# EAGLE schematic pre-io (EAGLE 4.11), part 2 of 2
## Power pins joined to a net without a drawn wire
-15V: A05.B2(-15V) A06.B2(-15V) A07.B2(-15V) A08.B2(-15V) A09.B2(-15V) A10.B2(-15V) A12.B2(-15V) A13.B2(-15V) A14.B2(-15V) A15.B2(-15V) A16.B2(-15V) A17.B2(-15V) A18.B2(-15V) A20.B2(-15V) A21.B2(-15V) A22.B2(-15V) A23.B2(-15V) A24.B2(-15V) A25.B2(-15V) A26.B2(-15V) A27.B2(-15V) A28.B2(-15V) A29.B2(-15V) A30.B2(-15V) A31.B2(-15V) A32.B2(-15V) A33.B2(-15V) A34.B2(-15V) A35.B2(-15V) A36.B2(-15V) A38.B2(-15V) A39.B2(-15V) A40.B2(-15V) B03.B2(-15V) B05.B2(-15V) B06.B2(-15V) B07.B2(-15V) B08.B2(-15V) B09.B2(-15V) B10.B2(-15V) B11.B2(-15V) B12.B2(-15V) B13.B2(-15V) B14.B2(-15V) B15.B2(-15V) B16.B2(-15V) B17.B2(-15V) B18.B2(-15V) B19.B2(-15V) B20.B2(-15V) B21.B2(-15V) B22.B2(-15V) B23.B2(-15V) B24.B2(-15V) B25.B2(-15V) B26.B2(-15V) B27.B2(-15V) B28.B2(-15V) B29.B2(-15V) B30.B2(-15V) B31.B2(-15V) B32.B2(-15V) B33.B2(-15V) B34.B2(-15V) B35.B2(-15V) B36.B2(-15V) B37.B2(-15V) B40.B2(-15V) C03.B2(-15V) C04.B2(-15V) C05.B2(-15V) C06.B2(-15V) C07.B2(-15V) C08.B2(-15V) C09.B2(-15V) C10.B2(-15V) C11.B2(-15V) C12.B2(-15V) C13.B2(-15V) C14.B2(-15V) C21.B2(-15V) C22.B2(B:-15V) C23.B2(-15V) C24.B2(-15V) C25.B2(B:-15V) C26.B2(-15V) C27.B2(B:-15V) C30.B2(-15V) C33.B2 C34.B2 C35.B2 C36.B2(-15V) C37.B2(-15V) C38.B2(-15V) C39.B2(-15V) D06.B2(-15V) D06A.B2(-15V) D07.B2(-15V) D08.B2(-15V) D09.B2(-15V) D10.B2(-15V) D11.B2(-15V) D12.B2(-15V) D13.B2(-15V) D14.B2(-15V) D15.B2(-15V) D16.B2(-15V) D17.B2(-15V) D18.B2(-15V) D19.B2(-15V) D20.B2(-15V) D21.B2(-15V) D22.B2(-15V) D23.B2 D24.B2 D25.B2 D26.B2 D27.B2(-15V) D33.B2 D34.B2 D35.B2 E03.B2(-15V) E05.B2(-15V) E06.B2(-15V) E07.B2(-15V) E09.B2(-15V) E10.B2(-15V) E11.B2(-15V) E12.B2(-15V) E13.B2(-15V) E14.B2(-15V) E15.B2(-15V) E16.B2(-15V) E17.B2(-15V) E18.B2(-15V) E19.B2(-15V) E20.B2(-15V) E21.B2 E22.B2 E23.B2 E24.B2 E25.B2 E26.B2 E27.B2 E28.B2 E33.B2 E34.B2 E35.B2 F03.B2(-15V) F05.B2(-15V) F06.B2(-15V) F07.B2(-15V) F08.B2(-15V) F09.B2(-15V) F10.B2(-15V) F11.B2(-15V) F12.B2(-15V) F13.B2(-15V) F14.B2(-15V) F15.B2(-15V) F16.B2(-15V) F17.B2(-15V) F18.B2(-15V) F19.B2(-15V) F20.B2(-15V) F21.B2 F22.B2 F22A.B2(-15V) F23.B2 F24.B2 F25.B2 F26.B2 F27.B2 F28.B2 F33.B2 F34.B2 F35.B2 F36.B2(-15V) F37.B2(-15V) F38.B2(-15V) F39.B2(-15V)
GND: A05.C2(GND) A06.C2(GND) A07.C2(GND) A08.C2(GND) A09.C2(GND) A10.C2(GND) A12.C2(GND) A13.C2(GND) A14.C2(GND) A15.C2(GND) A16.C2(K:GND) A17.C2(GND) A18.C2(GND) A20.C2(GND) A21.C2(GND) A22.C2(GND) A23.C2(GND) A24.C2(GND) A25.C2(GND) A26.C2(GND) A27.C2(GND) A29.C2(GND) A30.C2(GND) A31.C2(GND) A32.C2(GND) A33.C2(GND) A34.C2(GND) A35.C2(GND) A36.C2(GND) A38.C2(GND) A39.C2(GND) A40.C2(GND) B03.C2(GND) B05.C2(GND) B06.C2(GND) B07.C2(GND) B08.C2(GND) B09.C2(GND) B10.C2(GND) B11.C2(GND) B12.C2(GND) B13.C2(GND) B14.C2(GND) B15.C2(GND) B16.C2(GND) B17.C2(GND) B18.C2(GND) B19.C2(GND) B20.C2(GND) B21.C2(GND) B22.C2(GND) B23.C2(GND) B24.C2(GND) B25.C2(GND) B26.C2(GND) B28.C2(GND) B29.C2(GND) B30.C2(GND) B31.C2(GND) B32.C2(GND) B33.C2(GND) B34.C2(GND) B35.C2(GND) B36.C2(GND) B37.C2(GND) B40.C2(GND) C03.C2(GND) C05.C2(GND) C06.C2(GND) C07.C2(GND) C08.C2(GND) C09.C2(GND) C10.C2(GND) C11.C2(GND) C12.C2(GND) C13.C2(GND) C14.C2(GND) C21.C2(GND) C22.C2(C2:GND) C22.T2(T:GND) C22.U2(U:GND) C23.C2(GND) C24.C2(GND) C25.C2(C2:GND) C25.T2(T:GND) C25.U2(U:GND) C26.C2(GND) C27.C2(C2:GND) C27.T2(T:GND) C27.U2(U:GND) C30.C2(GND) C33.C2 C34.C2 C35.C2 C36.C2(GND) C37.C2(GND) C38.C2(K:GND) C39.C2(GND) C39.V2(V:GND) D06.C2(GND) D06A.C2(GND) D07.C2(GND) D08.C2(GND) D09.C2(GND) D10.C2(GND) D11.C2(GND) D12.C2(GND) D13.C2(GND) D14.C2(GND) D15.C2(GND) D16.C2(GND) D17.C2(GND) D18.C2(GND) D19.C2(GND) D20.C2(GND) D21.C2(GND) D22.C2(GND) D23.C2 D24.C2 D25.C2 D26.C2 D27.C2(GND) D33.C2 D34.C2 D35.C2 E03.C2(GND) E05.C2(GND) E05.V2(V:GND) E06.C2(GND) E07.C2(GND) E09.C2(GND) E10.C2(GND) E11.C2(GND) E12.C2(GND) E13.C2(GND) E14.C2(GND) E15.C2(GND) E16.C2(GND) E17.C2(GND) E18.C2(GND) E19.C2(GND) E20.C2(GND) E21.C2 E22.C2 E23.C2 E24.C2 E25.C2 E26.C2 E27.C2 E28.C2 E33.C2 E34.C2 E35.C2 F03.C2(GND) F05.C2(GND) F06.C2(GND) F07.C2(GND) F08.C2(GND) F09.C2(GND) F10.C2(GND) F11.C2(GND) F12.C2(GND) F13.C2(GND) F14.C2(GND) F15.C2(GND) F16.C2(GND) F17.C2(GND) F18.C2(GND) F19.C2(GND) F20.C2(GND) F21.C2 F22.C2 F22A.C2(GND) F23.C2 F24.C2 F25.C2 F26.C2 F27.C2 F28.C2 F33.C2 F34.C2 F35.C2 F36.C2(GND) F37.C2(K:GND) F38.C2(K:GND) F39.C2(K:GND)
VCC: A05.A2(VCC) A06.A2(VCC) A07.A2(VCC) A08.A2(VCC) A09.A2(VCC) A10.A2(VCC) A12.A2(VCC) A13.A2(VCC) A14.A2(VCC) A15.A2(VCC) A16.A2(VCC) A17.A2(VCC) A18.A2(VCC) A20.A2(VCC) A21.A2(VCC) A22.A2(VCC) A23.A2(VCC) A24.A2(VCC) A25.A2(VCC) A26.A2(VCC) A27.A2(VCC) A28.A2(VCC) A29.A2(VCC) A30.A2(VCC) A31.A2(VCC) A32.A2(VCC) A33.A2(VCC) A34.A2(VCC) A35.A2(VCC) A36.A2(VCC) A38.A2(VCC) A39.A2(VCC) A40.A2(VCC) B03.A2(VCC) B05.A2(VCC) B06.A2(VCC) B07.A2(VCC) B08.A2(VCC) B09.A2(VCC) B10.A2(VCC) B11.A2(VCC) B12.A2(VCC) B13.A2(VCC) B14.A2(VCC) B15.A2(VCC) B16.A2(VCC) B17.A2(VCC) B18.A2(VCC) B19.A2(VCC) B20.A2(VCC) B21.A2(VCC) B22.A2(VCC) B23.A2(VCC) B24.A2(VCC) B25.A2(VCC) B26.A2(VCC) B27.A2(VCC) B28.A2(VCC) B29.A2(VCC) B30.A2(VCC) B31.A2(VCC) B32.A2(VCC) B33.A2(VCC) B34.A2(VCC) B35.A2(VCC) B36.A2(VCC) B37.A2(VCC) B40.A2(VCC) C03.A2(VCC) C04.A2(VCC) C05.A2(VCC) C06.A2(VCC) C07.A2(VCC) C08.A2(VCC) C09.A2(VCC) C10.A2(VCC) C11.A2(VCC) C12.A2(VCC) C13.A2(VCC) C14.A2(VCC) C21.A2(VCC) C22.A2(C2:VCC) C23.A2(VCC) C24.A2(VCC) C25.A2(C2:VCC) C26.A2(VCC) C27.A2(C2:VCC) C30.A2(VCC) C33.A2 C34.A2 C35.A2 C36.A2(VCC) C37.A2(VCC) C38.A2(VCC) C39.A2(VCC) D06.A2(VCC) D06A.A2(VCC) D07.A2(VCC) D08.A2(VCC) D09.A2(VCC) D10.A2(VCC) D11.A2(VCC) D12.A2(VCC) D13.A2(VCC) D14.A2(VCC) D15.A2(VCC) D16.A2(VCC) D17.A2(VCC) D18.A2(VCC) D19.A2(VCC) D20.A2(VCC) D21.A2(VCC) D22.A2(VCC) D23.A2 D24.A2 D25.A2 D26.A2 D27.A2(VCC) D33.A2 D34.A2 D35.A2 E03.A2(VCC) E05.A2(VCC) E06.A2(VCC) E07.A2(VCC) E09.A2(VCC) E10.A2(VCC) E11.A2(VCC) E12.A2(VCC) E13.A2(VCC) E14.A2(VCC) E15.A2(VCC) E16.A2(VCC) E17.A2(VCC) E18.A2(VCC) E19.A2(VCC) E20.A2(VCC) E21.A2 E22.A2 E23.A2 E24.A2 E25.A2 E26.A2 E27.A2 E28.A2 E33.A2 E34.A2 E35.A2 F03.A2(VCC) F05.A2(VCC) F06.A2(VCC) F07.A2(VCC) F08.A2(VCC) F09.A2(VCC) F10.A2(VCC) F11.A2(VCC) F12.A2(VCC) F13.A2(VCC) F14.A2(VCC) F15.A2(VCC) F16.A2(VCC) F17.A2(VCC) F18.A2(VCC) F19.A2(VCC) F20.A2(VCC) F21.A2 F22.A2 F22A.A2(VCC) F23.A2 F24.A2 F25.A2 F26.A2 F27.A2 F28.A2 F33.A2 F34.A2 F35.A2 F36.A2(VCC) F37.A2(VCC) F38.A2(VCC) F39.A2(VCC)

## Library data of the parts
A01 A02 B01 B02 C01 C02 C28 D01 D02 D28 E01 E02 F01 F02 = dec-r:W023: One-sided 18 pin connector/cable.
A05-A07 B06 B07 C03 C06 E07 = dec-r:W050: Indicator Driver
A08 A10 A15 A26 A27 B15 B17 B24 B25 B36 C14 D06 D06A D07 D08 E09 E10 E11 E13 E14 F14 F36 = dec-r:R113: Diode Gate
A09 A17 A18 A24 A40 B08 B16 B33 B37 C05 C09 C13 C21 C24 C36 D18 F10-F13 F18-F20 = dec-r:R107: 7 Inverters
A12 A13 A39 B14 B21 B26 C08 = dec-r:R002: 5 Diode Networks
A14 A21 A23 A25 A34 A38 B13 B20 B23 C07 C10 C12 F07-F09 F15 F17 = dec-r:R111: Diode Gate
A16 A28 B27 C04 C38 F37-F39 = dec-r:R602: Dual Pulse Amplifier
A20 B03 B18 B19 B22 B29-B31 C37 D09 D10 = dec-r:R603: Triple Pulse Amplifier
A22 A33 A35 C11 E03 F06 F16 = dec-r:R001: 7 Diodes
A29-A32 B09 B10-B12 B28 B34 B35 D11-D16 D19 D20 E06 E12 E15-E20 F03 F05 = dec-r:R202: Dual Flip-Flop
A36 = dec-r:R302: Dual Delay (One Shot)
B05 B40 C30 F22A = dec-r:W005: 15 Clamped Loads
B32 = dec-r:R401: Variable Frequency Clock
C22 C25 C27 = dec-r:M517: M517 Negative Bus Converter
C23 C26 = dec-r:W512: Positive Level Converter
C33-C35 D23-D26 D33-D35 E21-E28 E33-E35 F21-F28 F33-F35 = dec-r:EMPTY: Empty Slot
C39 E05 = dec-r:W501: Negative Input Converter and Schmidt Trigger
D17 = dec-r:R151: Binary-to-Octal Decoder
D21 D22 D27 = dec-r:M507: M507 Negative Bus Converter

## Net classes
1 Supply: width 0.635 mm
